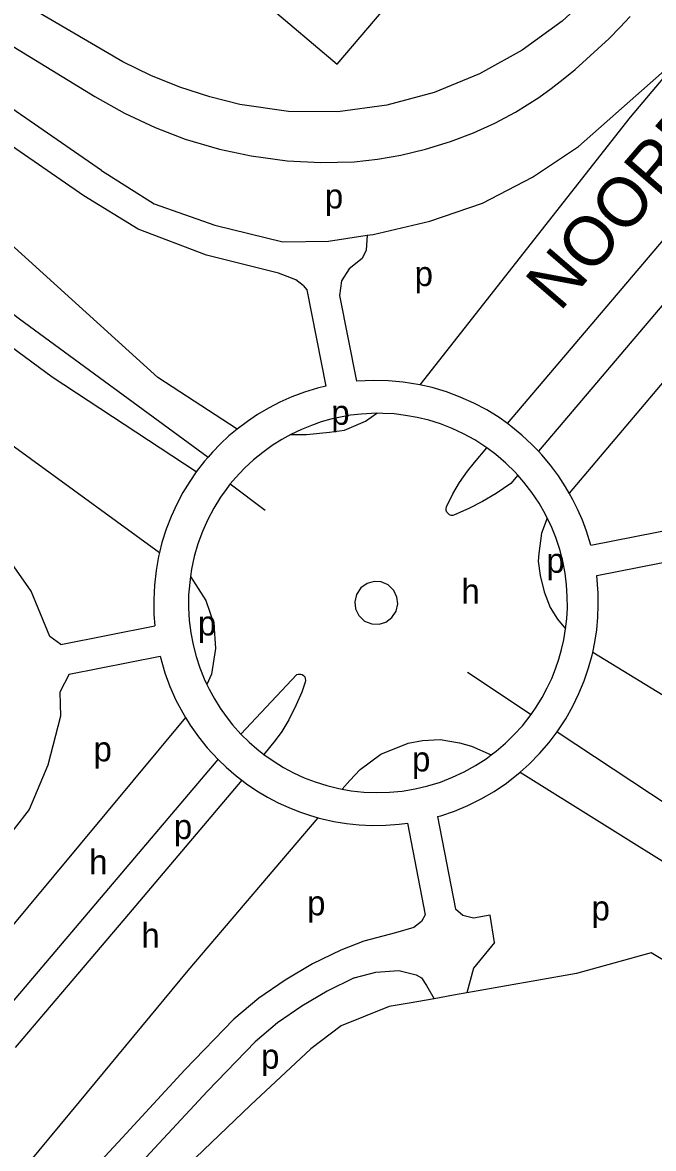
# Model space of a CAD drawing. Extents: x 155696 to 157795, y 382328 to 384028.
# Drawn here: x 157175 to 157277.3, y 382607.2 to 382789.6 of the extents above; entities that cross this region are included whole.
import ezdxf

# ---------------------------------------------------------------- set-up
doc = ezdxf.new("R2010")
doc.units = 0
for name, color, linetype in [('BLT_Basislijn', 7, 'Continuous'), ('BLT_Centroide', 7, 'Continuous'), ('BLT_Gemeentegrens', 7, 'Continuous'), ('BLT_Straatnaam_hoofdweg', 7, 'Continuous')]:
    doc.layers.add(name, color=color, linetype=linetype)

msp = doc.modelspace()

# ---------------------------------------------------------------- linework, layer by layer
at = {"layer": 'BLT_Basislijn'}
for p, q in [((157179.82, 382732.12), (157163.75, 382743.95)), ((157209.56, 382715.84), (157208.7, 382714.85)), ((157208.7, 382714.85), (157214.34, 382710.59)), ((157267.13, 382704.93), (157282.65, 382707.97)), ((157181.21, 382688.84), (157196.48, 382691.86)), ((157182.56, 382684.01), (157197.31, 382686.92)), ((157237.4, 382659.9), (157240.29, 382645.03)), ((157242.3, 382660.95), (157245.2, 382645.98)), ((157251.53, 382640.57), (157250.85, 382645.02))]:
    msp.add_line(p, q, dxfattribs=at)
for points in [[(157253.63, 382724.61), (157366.67, 382857.64), (157375.4, 382871.21), (157427.45, 382928.46)], [(157435.21, 382921.17), (157412.48, 382898.08), (157406.33, 382891.74), (157400.57, 382885.12), (157334.47, 382809.42), (157258.65, 382720.15)], [(157434.63, 382906.74), (157423.6, 382895.87), (157413.48, 382888.5), (157409.2, 382885.05), (157298.01, 382753.93), (157263.65, 382713.32)], [(157206.82, 382799.06), (157226.02, 382782.81), (157268.53, 382832.74)], [(157187.81, 382765.58), (157101.4, 382825.29), (157101.07, 382825.75), (157100.85, 382826.17), (157100.69, 382826.69), (157100.62, 382827.19), (157100.64, 382827.78), (157100.76, 382828.31), (157100.99, 382828.85), (157101.51, 382829.77)], [(157101.51, 382829.77), (157151.55, 382799.13), (157186.76, 382777.57)], [(157191.27, 382783.17), (157164.8, 382798.68), (157143.82, 382811.55), (157124.95, 382823.06), (157115.03, 382829.11)], [(157220.53, 382746.98), (157219.32, 382747.88), (157216.49, 382748.98), (157204.87, 382751.87), (157193.77, 382756.09), (157184.97, 382761.47), (157099.22, 382820.72), (157097.22, 382818.45)], [(157209.82, 382723.72), (157196.97, 382732.07), (157166.67, 382759.44), (157159.52, 382765.19), (157129.12, 382791.27), (157097.22, 382818.45)], [(157181.21, 382688.84), (157179.43, 382690.1), (157176.42, 382697.44), (157171.41, 382704.63), (157166.61, 382709.99), (157160.01, 382715.97), (157130.85, 382743.22), (157078.2, 382792.43), (157081.81, 382796.54)], [(157268.27, 382795.13), (157262.47, 382789.76), (157256.03, 382785.09), (157249.08, 382781.23), (157241.76, 382778.24)], [(157258.71, 382777.4), (157260.7, 382778.87), (157262.66, 382780.4), (157264.58, 382781.97), (157266.46, 382783.6), (157268.3, 382785.27), (157270.09, 382786.98), (157271.84, 382788.74), (157273.54, 382790.55)], [(157230.87, 382755.1), (157231.84, 382755.25), (157241.03, 382757.39), (157249.56, 382760.28), (157257.7, 382764.49), (157265.17, 382769.46), (157282.32, 382784.63)], [(157282.32, 382784.63), (157273.54, 382774.22), (157239.4, 382730.89)], [(157210.27, 382776.3), (157205.36, 382777.52), (157200.54, 382779.08), (157195.83, 382780.97), (157191.27, 382783.17)], [(157100.35, 382776.62), (157104.01, 382773.13), (157107.21, 382770.34), (157140.61, 382744.88), (157150.41, 382737.15), (157169.27, 382724.01), (157197.23, 382703.74)], [(157186.76, 382777.57), (157191.54, 382774.86), (157196.5, 382772.53), (157201.38, 382770.67), (157206.95, 382769.03), (157212.08, 382767.94), (157217.93, 382767.17), (157223.37, 382766.89), (157228.77, 382767.02), (157232.56, 382767.43), (157236.36, 382768.08), (157240.34, 382769.02), (157244.41, 382770.28), (157248.13, 382771.7), (157251.56, 382773.27), (157254.93, 382775.06), (157258.71, 382777.4)], [(157241.76, 382778.24), (157234.1, 382776.15), (157226.15, 382775.11), (157218.14, 382775.17), (157210.27, 382776.3)], [(157187.81, 382765.58), (157196.35, 382760.18), (157206.2, 382756.75), (157217.21, 382754.02), (157224.64, 382754.13), (157230.87, 382755.1)], [(157230.87, 382755.1), (157230.75, 382752.67), (157230.1, 382751.32), (157227.96, 382749.65), (157226.74, 382747.75), (157226.39, 382745.35), (157229.14, 382731.48)], [(157158.09, 382754.12), (157174.51, 382741.58), (157205.09, 382719.16)], [(157220.53, 382746.98), (157221.1, 382746.29), (157224.21, 382730.66)], [(157203.16, 382716.77), (157179.82, 382732.12)], [(157239.4, 382730.89), (157236.7, 382731.34), (157234.32, 382731.55), (157231.95, 382731.6), (157229.14, 382731.48)], [(157253.63, 382724.61), (157252.28, 382725.57), (157250.27, 382726.81), (157248.17, 382727.93), (157245.98, 382728.91), (157243.73, 382729.75), (157241.42, 382730.44), (157239.4, 382730.89)], [(157224.21, 382730.66), (157222.84, 382730.34), (157220.72, 382729.69), (157218.68, 382728.93), (157216.74, 382728.06), (157214.88, 382727.11), (157213.13, 382726.08), (157211.48, 382724.97), (157209.82, 382723.72)], [(157218.54, 382722.84), (157221.06, 382722.84), (157224.76, 382723.21), (157227.23, 382723.53), (157230.63, 382725.01), (157232.48, 382726.3)], [(157232.48, 382726.3), (157229.89, 382726.15), (157228.21, 382725.95), (157226.59, 382725.67), (157225.02, 382725.31), (157223.45, 382724.87), (157221.86, 382724.32), (157220.26, 382723.67), (157218.54, 382722.84)], [(157250.3, 382720.69), (157248.33, 382721.96), (157246.51, 382722.95), (157244.66, 382723.82), (157242.78, 382724.54), (157240.88, 382725.14), (157238.99, 382725.6), (157237.11, 382725.94), (157235.25, 382726.16), (157233.42, 382726.26), (157232.48, 382726.3)], [(157209.82, 382723.72), (157208.49, 382722.61), (157207.13, 382721.34), (157205.81, 382719.98), (157205.09, 382719.16)], [(157258.65, 382720.15), (157257.65, 382721.19), (157255.98, 382722.74), (157254.19, 382724.21), (157253.63, 382724.61)], [(157218.54, 382722.84), (157217.07, 382722.04), (157215.5, 382721.05), (157213.95, 382719.94), (157212.45, 382718.71), (157211.01, 382717.37), (157209.56, 382715.84)], [(157243.77, 382711.1), (157244.79, 382713.22), (157245.86, 382715.06), (157247.13, 382716.89), (157248.27, 382718.31), (157250.3, 382720.69)], [(157255.32, 382716.23), (157254.89, 382716.72), (157253.38, 382718.2), (157251.77, 382719.58), (157250.3, 382720.69)], [(157263.65, 382713.32), (157263.06, 382714.37), (157261.9, 382716.15), (157260.61, 382717.88), (157259.2, 382719.57), (157258.65, 382720.15)], [(157205.09, 382719.16), (157204.52, 382718.51), (157203.16, 382716.77)], [(157203.16, 382716.77), (157202.12, 382715.25), (157201.03, 382713.46), (157200.02, 382711.56), (157199.11, 382709.57), (157198.3, 382707.49), (157197.62, 382705.33), (157197.23, 382703.74)], [(157208.7, 382714.85), (157207.88, 382713.71)], [(157255.32, 382716.23), (157254.17, 382714.88), (157251.82, 382713.3), (157249.58, 382711.98), (157247.37, 382710.84), (157245.07, 382709.81)], [(157260.09, 382709.27), (157259.79, 382709.9), (157258.75, 382711.71), (157257.59, 382713.46), (157256.3, 382715.13), (157255.32, 382716.23)], [(157207.88, 382713.71), (157207.12, 382712.67), (157206.02, 382710.9), (157205.04, 382709.05), (157204.18, 382707.12), (157203.45, 382705.13), (157202.86, 382703.1), (157202.41, 382701.03), (157202.23, 382699.83)], [(157267.13, 382704.93), (157266.43, 382707.17), (157265.77, 382708.97), (157264.99, 382710.77), (157264.24, 382712.27), (157263.65, 382713.32)], [(157245.07, 382709.81), (157244.78, 382709.73), (157244.52, 382709.74), (157244.23, 382709.84), (157243.99, 382710.02), (157243.8, 382710.28), (157243.71, 382710.55), (157243.7, 382710.83), (157243.77, 382711.1)], [(157260.09, 382709.27), (157259.15, 382706.88), (157258.69, 382703.57), (157258.63, 382702.34), (157258.92, 382700.03), (157259.57, 382697.35), (157260.56, 382694.82), (157261.74, 382692.95), (157263.06, 382691.35)], [(157263.06, 382691.35), (157263.24, 382693.01), (157263.34, 382694.79), (157263.33, 382696.62), (157263.21, 382698.49), (157262.96, 382700.39), (157262.59, 382702.31), (157262.1, 382704.23), (157261.46, 382706.14), (157260.69, 382708.04), (157260.09, 382709.27)], [(157197.23, 382703.74), (157197.07, 382703.09), (157196.66, 382700.8), (157196.39, 382698.46), (157196.28, 382696.08), (157196.32, 382693.69), (157196.48, 382691.86)], [(157268.12, 382700.03), (157281.83, 382702.71), (157283.42, 382702.69), (157284.68, 382702.17), (157285.68, 382701.3), (157286.35, 382700.23), (157287.11, 382699.46), (157288.09, 382699.03), (157291.24, 382698.78)], [(157267.44, 382687.53), (157267.78, 382689.19), (157268.09, 382691.23), (157268.28, 382693.24), (157268.35, 382695.21), (157268.32, 382697.13), (157268.12, 382700.03)], [(157202.23, 382699.83), (157201.94, 382696.86), (157201.92, 382694.79), (157202.04, 382692.74), (157202.3, 382690.72), (157202.67, 382688.76), (157203.17, 382686.86), (157203.77, 382685.04), (157204.47, 382683.28), (157204.92, 382682.33)], [(157202.23, 382699.83), (157204.76, 382695.94), (157206.04, 382692.2), (157206.29, 382688.2), (157205.64, 382684.04), (157204.92, 382682.33)], [(157232.01, 382699.03), (157230.88, 382698.72), (157229.86, 382697.99), (157229.15, 382696.92), (157228.88, 382695.73), (157229.01, 382694.6), (157229.55, 382693.51), (157230.48, 382692.63), (157231.65, 382692.16), (157232.81, 382692.11)], [(157232.81, 382692.11), (157233.91, 382692.45), (157234.9, 382693.18), (157235.58, 382694.24), (157235.84, 382695.41), (157235.71, 382696.52), (157235.19, 382697.6), (157234.28, 382698.47), (157233.15, 382698.96), (157232.01, 382699.03)], [(157257.47, 382677.5), (157258.3, 382678.68), (157259.25, 382680.23), (157260.09, 382681.79), (157260.82, 382683.35), (157261.44, 382684.91), (157261.97, 382686.45), (157262.4, 382688), (157262.77, 382689.61), (157263.06, 382691.35)], [(157261.7, 382674.71), (157263.09, 382676.81), (157264.23, 382678.82), (157265.22, 382680.87), (157266.07, 382682.95), (157266.78, 382685.03), (157267.35, 382687.12), (157267.44, 382687.53)], [(157316.02, 382659.07), (157296.13, 382670.03), (157267.44, 382687.53)], [(157197.31, 382686.92), (157198.09, 382684.26), (157198.92, 382682.01), (157199.89, 382679.84), (157200.98, 382677.75), (157201.44, 382677.01)], [(157182.56, 382684.01), (157181.05, 382681.09), (157181.18, 382677.2), (157179.15, 382669.31), (157176.12, 382662.12), (157171.17, 382655.82), (157160.68, 382642.55), (157156.99, 382637.72)], [(157210.43, 382674.31), (157219.47, 382683.96)], [(157219.47, 382683.96), (157219.76, 382684.05), (157220.06, 382684.05), (157220.35, 382683.96), (157220.58, 382683.8), (157220.76, 382683.58), (157220.86, 382683.32), (157220.89, 382683.01), (157220.83, 382682.74)], [(157247.15, 382684.33), (157257.47, 382677.5)], [(157204.92, 382682.33), (157205.26, 382681.61), (157206.12, 382680.03), (157207.05, 382678.54), (157208.04, 382677.15), (157209.07, 382675.84), (157210.43, 382674.31)], [(157220.83, 382682.74), (157220.27, 382681.11), (157219.37, 382679.07), (157218.19, 382676.62), (157217.06, 382674.75), (157216, 382673.27), (157214.11, 382671.04)], [(157201.44, 382677.01), (157167.23, 382636), (157163.95, 382631.85)], [(157201.44, 382677.01), (157202.2, 382675.76), (157203.53, 382673.88), (157204.95, 382672.12), (157206.72, 382670.2)], [(157250.99, 382670.95), (157251.8, 382671.55), (157253.33, 382672.86), (157254.74, 382674.23), (157256.04, 382675.67), (157257.47, 382677.5)], [(157255.71, 382668.13), (157257.15, 382669.45), (157258.83, 382671.16), (157260.38, 382672.96), (157261.7, 382674.71)], [(157261.7, 382674.71), (157282.84, 382660.73), (157308.03, 382645.89)], [(157210.43, 382674.31), (157211.76, 382673.02), (157213.01, 382671.92), (157214.11, 382671.04)], [(157229.77, 382668.59), (157233.11, 382671.07), (157237.55, 382672.86), (157239.87, 382673.29), (157242.73, 382673.42), (157245.87, 382672.92), (157247.8, 382672.37), (157250.99, 382670.95)], [(157214.11, 382671.04), (157215.8, 382669.86), (157217.33, 382668.92), (157218.96, 382668.05), (157220.67, 382667.26), (157222.47, 382666.57), (157224.34, 382665.98), (157226.28, 382665.5), (157226.86, 382665.4)], [(157226.86, 382665.4), (157228.28, 382665.15), (157230.32, 382664.93), (157232.39, 382664.84), (157234.48, 382664.89), (157236.58, 382665.09), (157238.67, 382665.44), (157240.73, 382665.92), (157242.75, 382666.55), (157244.72, 382667.32), (157246.62, 382668.21), (157248.44, 382669.22), (157250.17, 382670.34), (157250.99, 382670.95)], [(157170.07, 382626.7), (157173.42, 382630.93), (157206.72, 382670.2)], [(157206.72, 382670.2), (157208.02, 382668.94), (157209.65, 382667.55), (157210.56, 382666.85)], [(157229.77, 382668.59), (157228.06, 382666.81), (157226.86, 382665.4)], [(157242.3, 382660.95), (157242.82, 382661.09), (157245.04, 382661.85), (157247.23, 382662.76), (157249.37, 382663.82), (157251.45, 382665.03), (157253.45, 382666.37), (157255.71, 382668.13)], [(157255.71, 382668.13), (157295.81, 382643.13)], [(157210.56, 382666.85), (157191.61, 382644.47), (157173.83, 382623.54)], [(157210.56, 382666.85), (157211.32, 382666.27), (157213.02, 382665.13), (157214.74, 382664.1), (157216.47, 382663.2), (157218.2, 382662.41), (157219.92, 382661.72), (157221.7, 382661.12), (157222.93, 382660.78)], [(157184.25, 382614.78), (157201.89, 382636.03), (157222.93, 382660.78)], [(157222.93, 382660.78), (157223.57, 382660.6), (157225.51, 382660.17), (157227.51, 382659.85), (157229.59, 382659.63), (157231.71, 382659.53), (157233.89, 382659.56), (157236.1, 382659.73), (157237.4, 382659.9)], [(157250.85, 382645.02), (157248.13, 382644.49), (157248.13, 382644.49), (157246.37, 382644.94), (157245.2, 382645.98)], [(157240.29, 382645.03), (157239.69, 382643.97), (157238.46, 382643.01), (157235.46, 382642.12), (157230.37, 382640.77), (157226.61, 382639.33), (157222.04, 382637.11), (157217.58, 382634.48), (157213.3, 382631.53), (157209.29, 382628.16), (157201.35, 382619.93), (157191.18, 382608.96)], [(157251.53, 382640.57), (157248.13, 382636.43), (157247.05, 382632.41)], [(157228.8, 382634.84), (157224.41, 382632.7), (157220.27, 382630.26), (157216.33, 382627.55), (157212.71, 382624.5), (157204.98, 382616.49), (157195.01, 382605.74)], [(157228.8, 382634.84), (157232.27, 382635.76), (157236.02, 382636.01), (157238.82, 382635.31), (157239.67, 382634.86), (157240.53, 382633.59), (157241.73, 382631.47)], [(157176.14, 382605), (157184.25, 382614.78)], [(157191.18, 382608.96), (157182.8, 382599.92)]]:
    msp.add_lwpolyline(points, dxfattribs=at)
at = {"layer": 'BLT_Gemeentegrens'}
for points in [[(157288.98, 382631.66), (157283.87, 382634.73), (157276.93, 382638.89), (157264.81, 382635.53), (157247.05, 382632.41)], [(157247.05, 382632.41), (157244.9, 382632.03)], [(157241.73, 382631.47), (157237.68, 382630.76), (157234.44, 382630.19), (157226.69, 382627.08), (157221.78, 382623.36), (157211.98, 382614.24), (157199.26, 382602.09), (157095.83, 382498.79)], [(157244.9, 382632.03), (157241.73, 382631.47)]]:
    msp.add_lwpolyline(points, dxfattribs=at)

# ---------------------------------------------------------------- texts
at = {"layer": 'BLT_Centroide'}
for s, p in [('p', (157224.03, 382759.44)), ('p', (157238.58, 382746.88)), ('p', (157225.07, 382724.41)), ('p', (157259.94, 382700.44)), ('h', (157246.16, 382695.46)), ('p', (157203.45, 382690.29)), ('p', (157186.53, 382669.91)), ('p', (157238.16, 382668.28)), ('p', (157199.55, 382657.33)), ('h', (157185.83, 382651.6)), ('p', (157221.15, 382644.97)), ('p', (157267.26, 382644.15)), ('h', (157194.28, 382639.73)), ('p', (157213.69, 382620.14))]:
    msp.add_text(s, height=4, dxfattribs=at).set_placement(p)
at = {"layer": 'BLT_Straatnaam_hoofdweg'}
msp.add_text('NOORD BRABANTLAAN', height=8, rotation=49.2897, dxfattribs=at).set_placement((157262.12, 382742.59))

doc.saveas('drawing.dxf')
